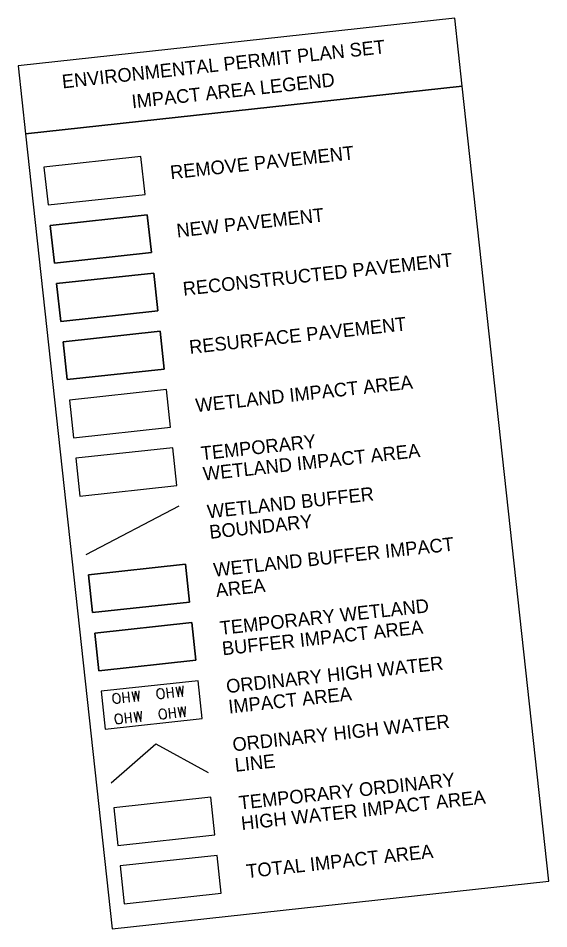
# Model space of a CAD drawing. Extents: x 1509538 to 1510847, y 401283 to 402022.
# Drawn here: x 1510737.8 to 1510846.6, y 401282.9 to 401469.4 of the extents above; entities that cross this region are included whole.
import ezdxf

# ---------------------------------------------------------------- set-up
doc = ezdxf.new("R2010")
doc.units = 0
for name, color, linetype in [('Default', 7, 'Continuous'), ('LAWE', 7, 'Continuous'), ('LAWE_P', 7, 'Continuous'), ('Level 1', 7, 'Continuous'), ('Level 11', 7, 'Continuous'), ('Level 12', 7, 'Continuous'), ('Level 2', 7, 'Continuous'), ('Level 3', 7, 'Continuous'), ('Level 4', 7, 'Continuous'), ('Level 6', 7, 'Continuous'), ('Level 9', 7, 'Continuous'), ('NBL1', 7, 'Continuous')]:
    doc.layers.add(name, color=color, linetype=linetype)

msp = doc.modelspace()

# ---------------------------------------------------------------- linework, layer by layer
at = {"layer": 'Default'}
for points in [[(1510752.22, 401355.37), (1510772.1, 401357.54), (1510772.95, 401349.79), (1510753.07, 401347.62)], [(1510753.52, 401343.44), (1510773.4, 401345.61), (1510774.25, 401337.86), (1510754.37, 401335.69)]]:
    msp.add_lwpolyline(points, close=True, dxfattribs=at)
for points in [[(1510753.07, 401347.62), (1510772.95, 401349.79), (1510772.1, 401357.54), (1510752.22, 401355.37), (1510753.07, 401347.62)], [(1510754.37, 401335.69), (1510774.25, 401337.86), (1510773.4, 401345.61), (1510753.52, 401343.44), (1510754.37, 401335.69)]]:
    msp.add_lwpolyline(points, dxfattribs=at)
at = {"layer": 'LAWE'}
msp.add_lwpolyline([(1510756.87, 401312.73), (1510766.05, 401320.77), (1510776.75, 401314.89)], dxfattribs=at)
at = {"layer": 'LAWE_P'}
for p, q in [((1510759.23, 401331.23), (1510759.45, 401329.14)), ((1510760.64, 401329.27), (1510760.41, 401331.36)), ((1510768.25, 401332.22), (1510768.47, 401330.13)), ((1510769.54, 401331.31), (1510768.36, 401331.18)), ((1510769.66, 401330.26), (1510769.43, 401332.34)), ((1510760.52, 401330.33), (1510759.34, 401330.2)), ((1510768.7, 401328.04), (1510768.93, 401325.95)), ((1510770.11, 401326.08), (1510769.89, 401328.17)), ((1510759.68, 401327.06), (1510759.91, 401324.97)), ((1510760.98, 401326.15), (1510759.8, 401326.02)), ((1510761.09, 401325.1), (1510760.87, 401327.19)), ((1510770, 401327.13), (1510768.81, 401327))]:
    msp.add_line(p, q, dxfattribs=at)
msp.add_lwpolyline([(1510755.67, 401323.76), (1510775.55, 401325.93), (1510774.7, 401333.68), (1510754.82, 401331.52)], close=True, dxfattribs=at)
for points in [[(1510757.78, 401331.07), (1510757.94, 401331.09), (1510758.24, 401331.01), (1510758.54, 401330.69), (1510758.65, 401330.29), (1510758.69, 401329.91), (1510758.67, 401329.49), (1510758.43, 401329.12), (1510758.17, 401329), (1510758.01, 401328.99), (1510757.75, 401329.04), (1510757.44, 401329.36), (1510757.33, 401329.76), (1510757.28, 401330.14), (1510757.3, 401330.57), (1510757.54, 401330.95), (1510757.78, 401331.07)], [(1510761.1, 401331.44), (1510761.66, 401329.38), (1510761.86, 401331.52), (1510762.51, 401329.48), (1510762.65, 401331.61)], [(1510766.8, 401332.06), (1510766.96, 401332.08), (1510767.26, 401331.99), (1510767.56, 401331.67), (1510767.67, 401331.27), (1510767.71, 401330.89), (1510767.69, 401330.47), (1510767.45, 401330.1), (1510767.19, 401329.99), (1510767.03, 401329.97), (1510766.77, 401330.03), (1510766.46, 401330.34), (1510766.34, 401330.74), (1510766.3, 401331.12), (1510766.32, 401331.56), (1510766.56, 401331.93), (1510766.8, 401332.06)], [(1510770.12, 401332.42), (1510770.68, 401330.37), (1510770.88, 401332.5), (1510771.53, 401330.46), (1510771.67, 401332.59)], [(1510761.56, 401327.26), (1510762.11, 401325.21), (1510762.31, 401327.34), (1510762.97, 401325.3), (1510763.1, 401327.43)], [(1510767.26, 401327.88), (1510767.42, 401327.9), (1510767.71, 401327.82), (1510768.01, 401327.5), (1510768.12, 401327.1), (1510768.16, 401326.72), (1510768.14, 401326.3), (1510767.9, 401325.92), (1510767.65, 401325.81), (1510767.48, 401325.8), (1510767.23, 401325.85), (1510766.91, 401326.17), (1510766.8, 401326.57), (1510766.76, 401326.95), (1510766.78, 401327.38), (1510767.02, 401327.76), (1510767.26, 401327.88)], [(1510770.58, 401328.24), (1510771.13, 401326.19), (1510771.33, 401328.33), (1510771.99, 401326.29), (1510772.12, 401328.41)], [(1510758.24, 401326.9), (1510758.4, 401326.92), (1510758.69, 401326.83), (1510758.99, 401326.52), (1510759.1, 401326.11), (1510759.14, 401325.73), (1510759.12, 401325.32), (1510758.88, 401324.94), (1510758.63, 401324.83), (1510758.46, 401324.81), (1510758.21, 401324.87), (1510757.89, 401325.18), (1510757.78, 401325.59), (1510757.74, 401325.96), (1510757.76, 401326.4), (1510758, 401326.77), (1510758.24, 401326.9)]]:
    msp.add_lwpolyline(points, dxfattribs=at)
at = {"layer": 'Level 1'}
for p, q in [((1510766.9, 401405.26), (1510747.02, 401403.09)), ((1510767.75, 401397.5), (1510766.9, 401405.26)), ((1510747.02, 401403.09), (1510747.86, 401395.34)), ((1510747.86, 401395.34), (1510767.75, 401397.5))]:
    msp.add_line(p, q, dxfattribs=at)
for points in [[(1510747.86, 401395.34), (1510767.75, 401397.5), (1510766.9, 401405.26), (1510747.02, 401403.09)], [(1510747.02, 401403.09), (1510766.9, 401405.26), (1510767.75, 401397.5), (1510747.86, 401395.34)]]:
    msp.add_lwpolyline(points, close=True, dxfattribs=at)
msp.add_lwpolyline([(1510747.86, 401395.34), (1510767.75, 401397.5), (1510766.9, 401405.26), (1510747.02, 401403.09), (1510747.86, 401395.34)], dxfattribs=at)
at = {"layer": 'Level 11'}
msp.add_lwpolyline([(1510749.16, 401383.41), (1510769.05, 401385.58), (1510768.2, 401393.33), (1510748.32, 401391.16)], close=True, dxfattribs=at)
msp.add_lwpolyline([(1510749.16, 401383.41), (1510769.05, 401385.58), (1510768.2, 401393.33), (1510748.32, 401391.16), (1510749.16, 401383.41)], dxfattribs=at)
at = {"layer": 'Level 12'}
msp.add_line((1510751.77, 401359.55), (1510770.8, 401369.47), dxfattribs=at)
msp.add_lwpolyline([(1510750.47, 401371.48), (1510770.35, 401373.65), (1510769.5, 401381.4), (1510749.62, 401379.23)], close=True, dxfattribs=at)
msp.add_lwpolyline([(1510750.47, 401371.48), (1510770.35, 401373.65), (1510769.5, 401381.4), (1510749.62, 401379.23), (1510750.47, 401371.48)], dxfattribs=at)
at = {"layer": 'Level 2'}
for points in [[(1510746.56, 401407.27), (1510766.45, 401409.43), (1510765.6, 401417.19), (1510745.72, 401415.02)], [(1510745.72, 401415.02), (1510765.6, 401417.19), (1510766.45, 401409.43), (1510746.56, 401407.27)]]:
    msp.add_lwpolyline(points, close=True, dxfattribs=at)
msp.add_lwpolyline([(1510746.56, 401407.27), (1510766.45, 401409.43), (1510765.6, 401417.19), (1510745.72, 401415.02), (1510746.56, 401407.27)], dxfattribs=at)
msp.add_lwpolyline([(1510746.56, 401407.27), (1510766.45, 401409.43), (1510765.6, 401417.19), (1510745.72, 401415.02), (1510746.56, 401407.27)], dxfattribs=at)
at = {"layer": 'Level 3'}
for points in [[(1510745.26, 401419.2), (1510765.15, 401421.36), (1510764.3, 401429.12), (1510744.42, 401426.95)], [(1510744.42, 401426.95), (1510764.3, 401429.12), (1510765.15, 401421.36), (1510745.26, 401419.2)]]:
    msp.add_lwpolyline(points, close=True, dxfattribs=at)
at = {"layer": 'Level 4'}
msp.add_lwpolyline([(1510743.96, 401431.13), (1510763.85, 401433.29), (1510763, 401441.05), (1510743.12, 401438.88)], close=True, dxfattribs=at)
msp.add_lwpolyline([(1510743.96, 401431.13), (1510763.85, 401433.29), (1510763, 401441.05), (1510743.12, 401438.88), (1510743.96, 401431.13)], dxfattribs=at)
at = {"layer": 'Level 6'}
msp.add_lwpolyline([(1510758.27, 401299.9), (1510778.15, 401302.07), (1510777.31, 401309.82), (1510757.42, 401307.66)], close=True, dxfattribs=at)
msp.add_lwpolyline([(1510758.27, 401299.9), (1510778.15, 401302.07), (1510777.31, 401309.82), (1510757.42, 401307.66), (1510758.27, 401299.9)], dxfattribs=at)
at = {"layer": 'Level 9'}
msp.add_lwpolyline([(1510759.57, 401287.97), (1510779.45, 401290.14), (1510778.61, 401297.89), (1510758.72, 401295.73)], close=True, dxfattribs=at)
at = {"layer": 'NBL1'}
for points in [[(1510739.35, 401445.71), (1510828.82, 401455.47), (1510827.31, 401469.38), (1510737.84, 401459.63)], [(1510757.11, 401282.85), (1510846.58, 401292.61), (1510828.82, 401455.47), (1510739.35, 401445.71)]]:
    msp.add_lwpolyline(points, close=True, dxfattribs=at)

# ---------------------------------------------------------------- texts
at = {"layer": 'Default'}
for s, p in [('WETLAND BUFFER IMPACT ', (1510778.02, 401354.97)), ('AREA', (1510778.47, 401350.79)), ('TEMPORARY WETLAND', (1510779.32, 401343.04)), ('BUFFER IMPACT AREA', (1510779.77, 401338.86))]:
    msp.add_text(s, height=2.8, rotation=6.2212, dxfattribs=at).set_placement(p)
at = {"layer": 'LAWE_P'}
for s, p in [('ORDINARY HIGH WATER ', (1510780.62, 401331.11)), ('IMPACT AREA', (1510781.07, 401326.93)), ('ORDINARY HIGH WATER ', (1510781.92, 401319.18)), ('LINE', (1510782.37, 401315))]:
    msp.add_text(s, height=2.8, rotation=6.2215, dxfattribs=at).set_placement(p)
at = {"layer": 'Level 1'}
msp.add_text('RESURFACE PAVEMENT', height=2.8, rotation=6.2215, dxfattribs=at).set_placement((1510773.04, 401400.6))
at = {"layer": 'Level 11'}
msp.add_text('WETLAND IMPACT AREA', height=2.8, rotation=6.2212, dxfattribs=at).set_placement((1510774.34, 401388.67))
at = {"layer": 'Level 12'}
for s, p in [('TEMPORARY', (1510775.42, 401378.83)), ('WETLAND IMPACT AREA', (1510775.87, 401374.65)), ('WETLAND BUFFER ', (1510776.72, 401366.9)), ('BOUNDARY', (1510777.17, 401362.72))]:
    msp.add_text(s, height=2.8, rotation=6.2212, dxfattribs=at).set_placement(p)
at = {"layer": 'Level 2'}
msp.add_text('RECONSTRUCTED PAVEMENT', height=2.8, rotation=6.2215, dxfattribs=at).set_placement((1510771.74, 401412.53))
at = {"layer": 'Level 3'}
msp.add_text('NEW PAVEMENT', height=2.8, rotation=6.2215, dxfattribs=at).set_placement((1510770.44, 401424.46))
at = {"layer": 'Level 4'}
msp.add_text('REMOVE PAVEMENT', height=2.8, rotation=6.2215, dxfattribs=at).set_placement((1510769.14, 401436.38))
at = {"layer": 'Level 6'}
for s, p in [('TEMPORARY ORDINARY', (1510783.22, 401307.25)), ('HIGH WATER IMPACT AREA', (1510783.67, 401303.07))]:
    msp.add_text(s, height=2.8, rotation=6.2215, dxfattribs=at).set_placement(p)
at = {"layer": 'Level 9'}
msp.add_text('TOTAL IMPACT AREA', height=2.8, rotation=6.2215, dxfattribs=at).set_placement((1510784.75, 401293.23))
at = {"layer": 'NBL1'}
for s, p in [('ENVIRONMENTAL PERMIT PLAN SET', (1510746.96, 401454.99)), ('IMPACT AREA LEGEND', (1510761.25, 401450.91))]:
    msp.add_text(s, height=2.8, rotation=6.2215, dxfattribs=at).set_placement(p)

doc.saveas('drawing.dxf')
